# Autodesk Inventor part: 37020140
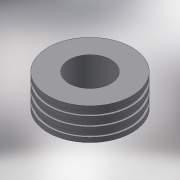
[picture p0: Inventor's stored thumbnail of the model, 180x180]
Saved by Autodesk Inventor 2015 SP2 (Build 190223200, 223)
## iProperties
Created: 2017-08
Part Number: 37020140
Material: Generic
Description: PLASSON MAN HOLE ADAPTOR 140
Document SubType Name: Modeling
Designer: Кирилл
Density: 1 g/cm^3
Appearance: Default
Author: Кирилл
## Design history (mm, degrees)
derived "37020-477207.ipt"
feature "Solid1::37020-477207.ipt"
tag "TaggingFeature1"
body "Solid1"
other parameters: "d0" = 135, "d1" = 254, "d2" = 241.3, "d3" = 123, "d6" = 39, "L_" = 135, "d_1" = 123, "D_" = 254, "H_" = 39
